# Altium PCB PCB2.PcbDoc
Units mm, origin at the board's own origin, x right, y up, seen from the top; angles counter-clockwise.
Board outline 152.4 x 101.6 mm, 2 copper layers (Top Layer, Bottom Layer); 14 components, 12 nets, 32 pads, 0 vias.
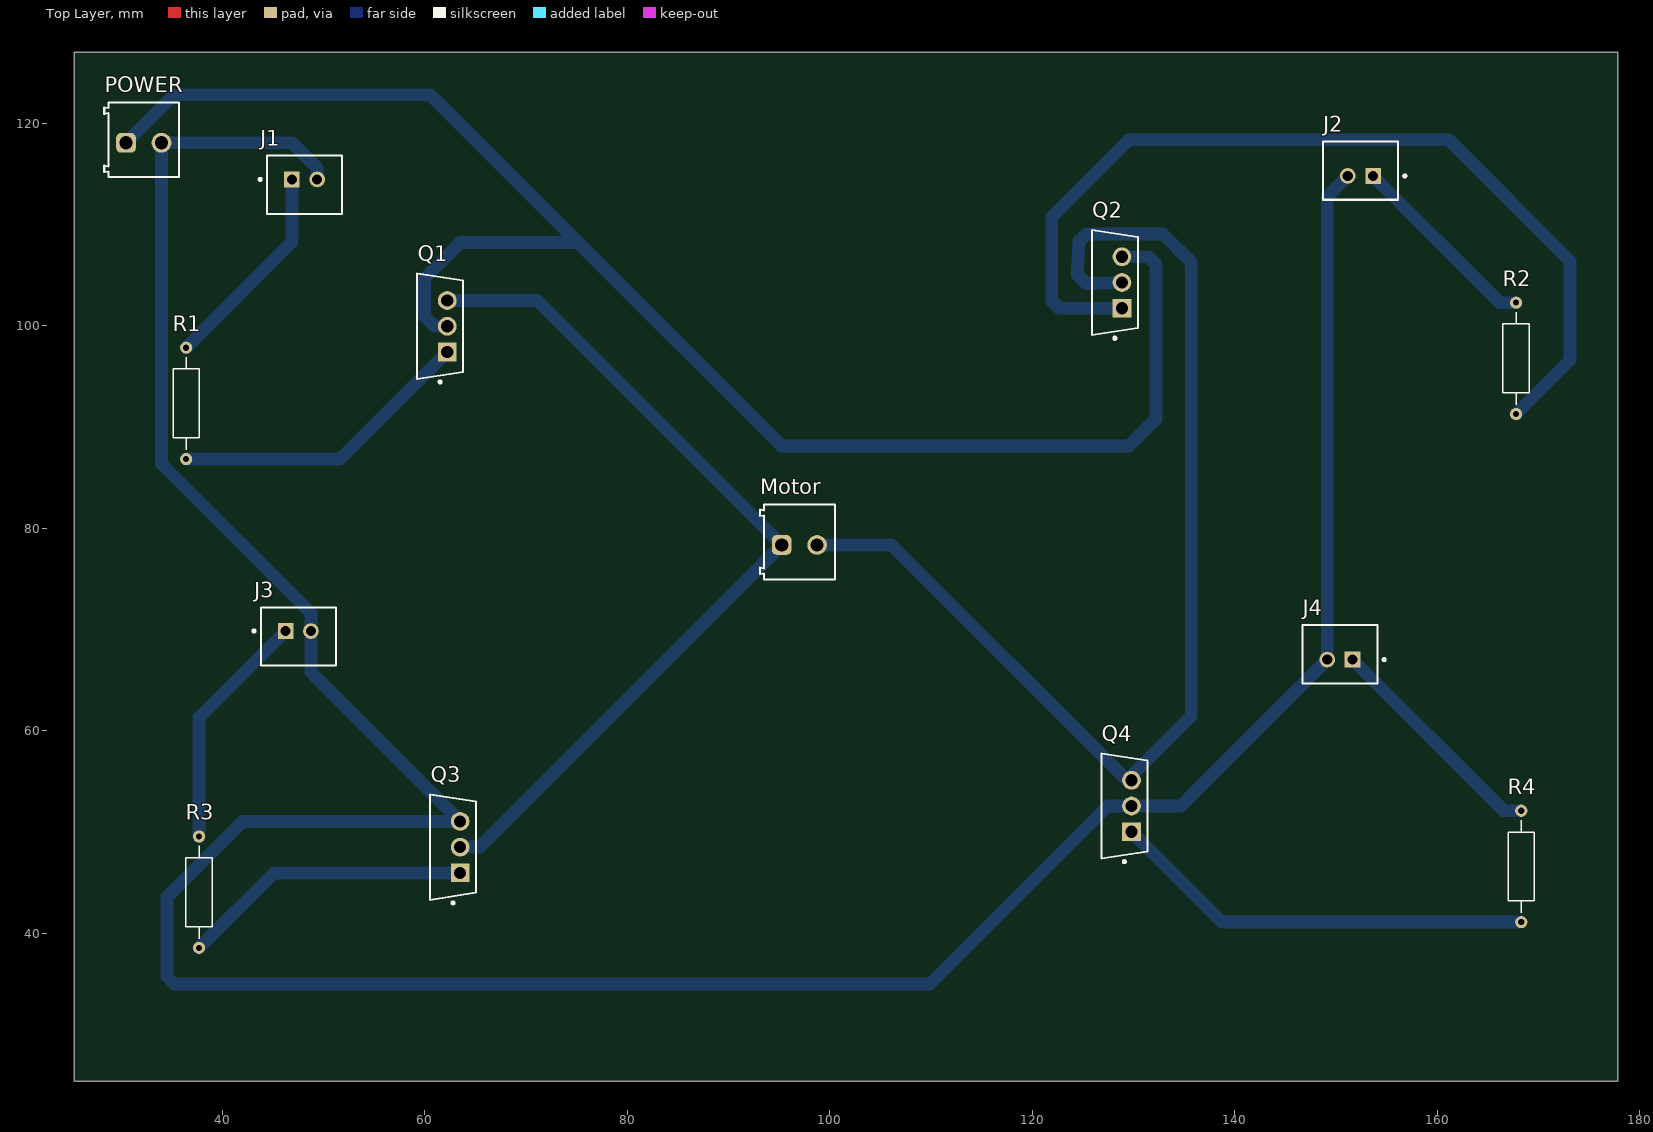
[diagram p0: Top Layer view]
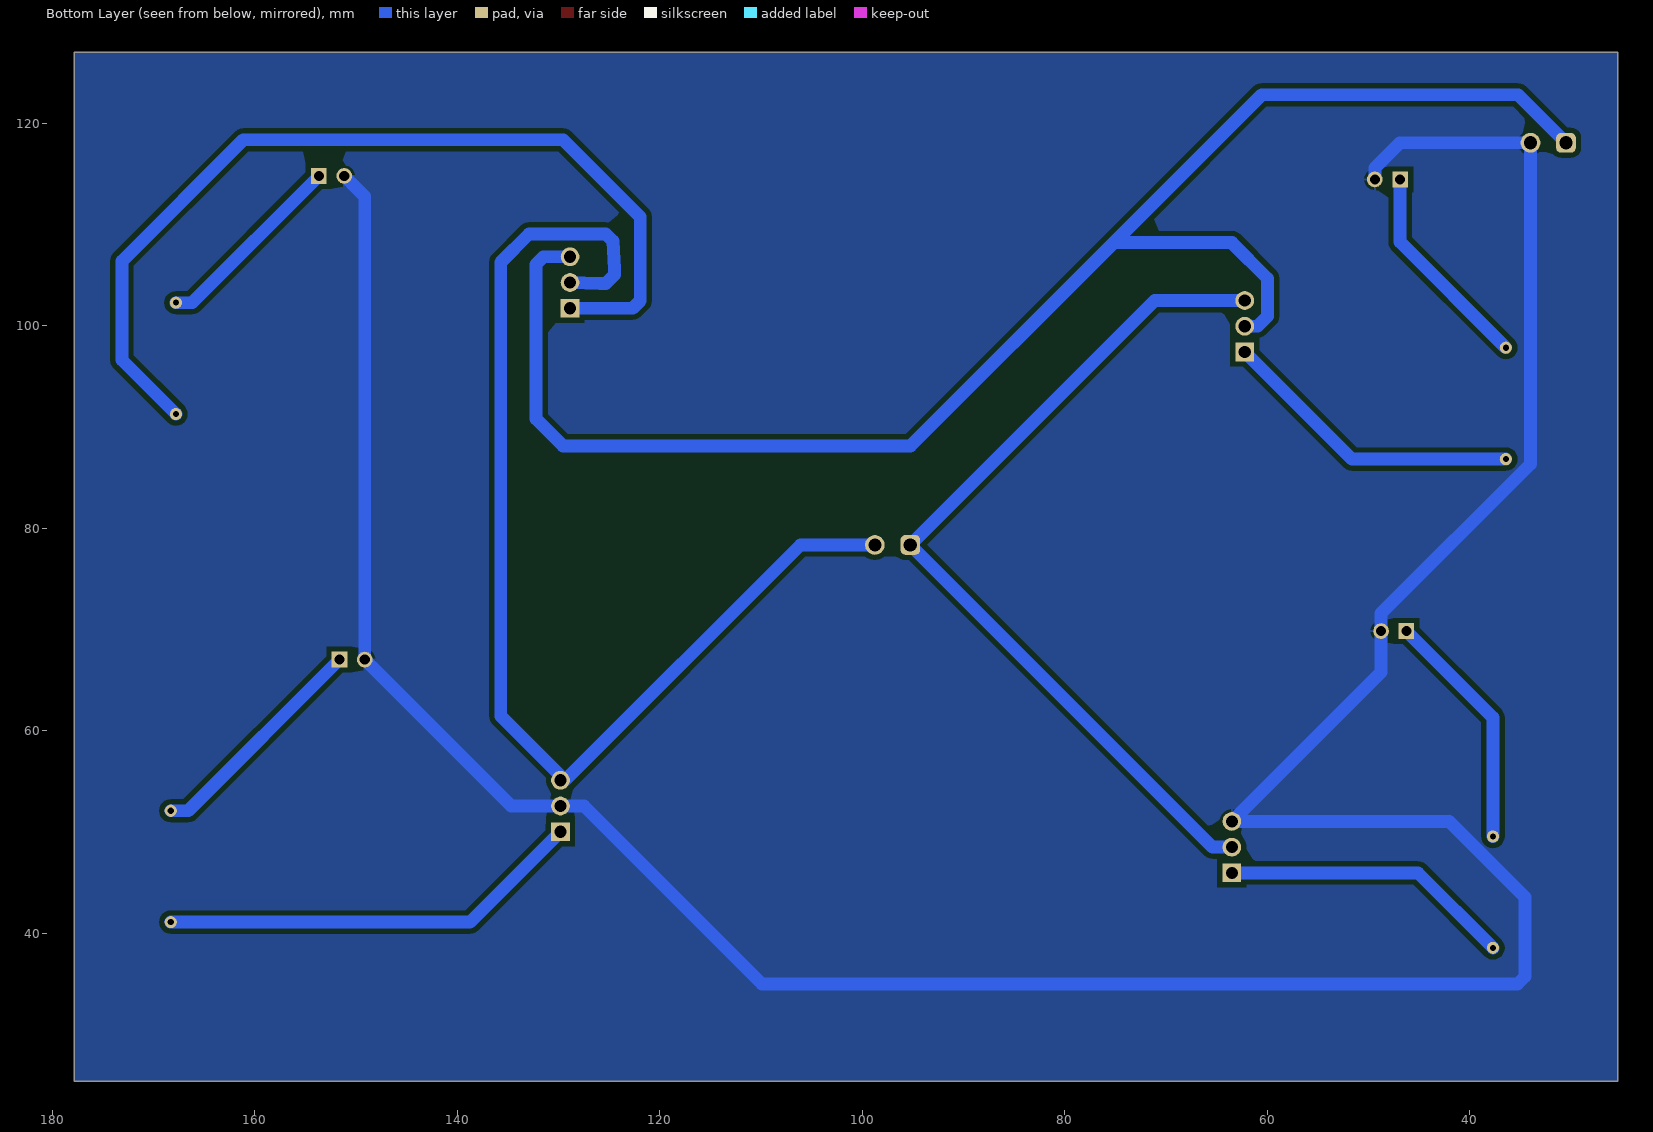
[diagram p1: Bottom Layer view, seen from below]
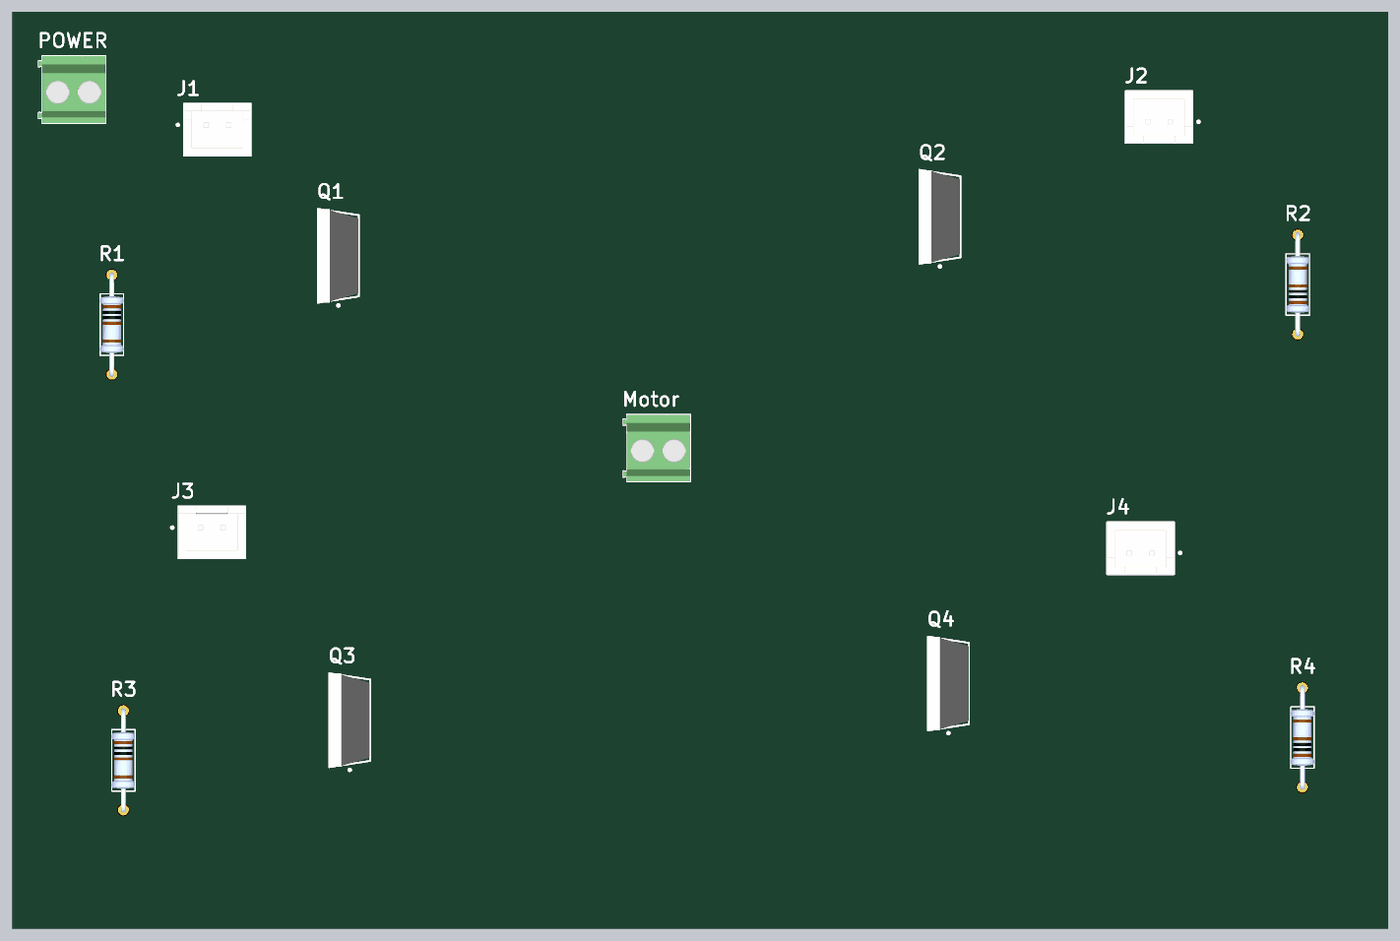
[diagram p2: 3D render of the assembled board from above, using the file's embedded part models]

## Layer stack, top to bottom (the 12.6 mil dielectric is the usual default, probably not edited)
Top Solder: solder mask 0.0102, Solder Resist, Dk 3.5
Top Layer: signal copper 0.0356
Dielectric 1: dielectric 0.32, FR-4, Dk 4.8
Bottom Layer: signal copper 0.0356
Bottom Solder: solder mask 0.0102, Solder Resist, Dk 3.5

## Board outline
25.4,25.4 177.8,25.4 177.8,127 25.4,127

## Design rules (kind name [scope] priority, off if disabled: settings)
Clearance [All] p1: gap=0.5 ignorepadtopadclearanceinfootprint=FALSE
PolygonConnect [All] p1: connectstyle=Relief reliefconductorwidth=0.254 reliefentries=4 polygonreliefangle="90 Angle" airgapwidth=0.254
RoutingVias [All] p1: holewidth=0.711 width=1.27 viastyle="Through Hole" minholewidth=0.711 minwidth=1.27 maxholewidth=0.711 maxwidth=1.27
SolderMaskExpansion [All] p1: expansion=0.102 istentingtop=FALSE
SupplyNets "Schematic Supply Nets_1" [InNet('VCC')] p1: voltage=0.000
SupplyNets "Schematic Supply Nets" [InNet('GND')] p2: voltage=0.000
Width [All] p1: maxlimit=2 minlimit=0.254 preferedwidth=1.27 toplayer_maxwidth=0.254 toplayer_prefwidth=0.254 bottomlayer_minwidth=1.27 minimp=50.000000 maximp=50.000000 favimp=50.000000
30 further rules are at their usual default settings.

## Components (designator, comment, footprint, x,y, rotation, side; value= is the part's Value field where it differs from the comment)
J1 "B2B-XH-A(LF)(SN)" "JST Connector" 48.133,113.919 r0 top
J2 "B2B-XH-A(LF)(SN)" "JST Connector" 152.4,115.316 r180 top
J3 "B2B-XH-A(LF)(SN)" "JST Connector" 47.518,69.325 r0 top
J4 "B2B-XH-A(LF)(SN)" "JST Connector" 150.368,67.564 r180 top
Motor "691214110002" "Terminal block" 97,78.659 r0 top
POWER "691214110002" "Terminal block" 32.258,118.364 r0 top
Q1 "IRF4905PBF" "Mosfet P-Ch" 61.525,99.949 r180 top
Q2 "IRF4905PBF" "Mosfet P-Ch" 128.143,104.267 r180 top
Q3 "IRLZ44NPbF" "MOSFET N-CH 55V 47A TO220AB" 62.795,48.514 r180 top
Q4 "IRLZ44NPbF" "MOSFET N-CH 55V 47A TO220AB" 129.089,52.578 r180 top
R1 "Resistor" Resistor 36.449,92.329 r270 top value=10K
R2 "Resistor" Resistor 167.767,96.774 r90 top value=10K
R3 "Resistor" Resistor 37.719,44.069 r270 top value=10K
R4 "Resistor" Resistor 168.275,46.609 r90 top value=10K

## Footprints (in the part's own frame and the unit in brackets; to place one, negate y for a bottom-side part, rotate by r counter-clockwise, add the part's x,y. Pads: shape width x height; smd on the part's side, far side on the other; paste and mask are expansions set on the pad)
"JST Connector" [mm] "FP-B2B-XH-A_LF_SN-MFG"
  rect 1.55x1.55 hole 1 paste-2539.97 mask+0: 1(-1.25,0.525)
  round 1.55 hole 1 paste-2539.97 mask+0: 2(1.25,0.525)
  silkscreen extent -4.5,-2.87 3.7,2.88, body extent -3.8,-2.98 3.8,2.98, height 0.25
"MOSFET N-CH 55V 47A TO220AB" [mm]
  rect 1.85x1.85 hole 1.2 paste-2539.97 mask+0: 1(-0.705,2.54)
  round 1.85 hole 1.2 paste-2539.97 mask+0: 2(-0.705,0) 3(-0.705,-2.54)
  silkscreen extent -2.28,-5.2 2.27,5.62, body extent -2.37,-5.55 2.37,5.55, height 0.25
"Mosfet P-Ch" [mm] "FP-PG-TO220-3-MFG"
  rect 1.85x1.85 hole 1.2 paste-2539.97 mask+0: 1(-0.705,2.54)
  round 1.85 hole 1.2 paste-2539.97 mask+0: 2(-0.705,0) 3(-0.705,-2.54)
  silkscreen extent -2.28,-5.2 2.27,5.62, body extent -2.37,-5.55 2.37,5.55, height 0.25
Resistor [mm]
  round 1.2 hole 0.6: 1(-5.5,0) 2(5.5,0)
  silkscreen extent -4.58,-1.3 4.58,1.3, body extent -5.77,-1.3 5.77,1.3, height 2.6
"Terminal block" [mm] "3.50 mm Horizontal Entry Modular, 2p"
  rrect50% 1.95x1.95 hole 1.3: 1(-1.75,-0.3)
  round 1.95 hole 1.3: 2(1.75,-0.3)
  silkscreen extent -3.9,-3.7 3.5,3.7, body extent -3.95,-3.7 3.5,3.7, height 8.55

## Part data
J1 J2 J3 J4: library part "jst connector", "CONN HEADER VERT 2POS 2.5MM", Color=Natural, Contact Resistance=20mR, Current Rating=3A, Housing Color=White, Insulation Resistance=1GR, Max Operating Temperature=85°C, Max Voltage Rating (AC)=250V, Min Operating Temperature=-25°C
Motor POWER: library part "Terminal block", Color="Blue, Green", Current=10A, Max Operating Temperature=105°C, Min Operating Temperature=-40°C, Voltage=300V
Q1 Q2: library part "Mosfet P-CH", "MOSFET P-CH 55V 74A TO-220AB", Case/Package=TO-220, Continuous Drain Current (ID)=74A, Drain to Source Breakdown Voltage=-55V, Drain to Source Resistance=20mR, Gate to Source Voltage (Vgs)=20V, Input Capacitance=3.4nF, Max Operating Temperature=175°C, Max Power Dissipation=200W, Min Operating Temperature=-55°C, Threshold Voltage=-4V
Q3 Q4: library part "MOSFET N-CH 55V 47A TO220AB", Case/Package=TO-220, Continuous Drain Current (ID)=47A, Drain to Source Breakdown Voltage=55V, Drain to Source Resistance=35mR, Gate to Source Voltage (Vgs)=16V, Input Capacitance=1.7nF, Max Operating Temperature=175°C, Max Power Dissipation=110W, Min Operating Temperature=-55°C, Threshold Voltage=2V
R1 R2 R3 R4: "10.2 kOhms Â±1% 0.25W, 1/4W Through Hole Resistor Axial - Metal Film", Package="Axial Yageo"

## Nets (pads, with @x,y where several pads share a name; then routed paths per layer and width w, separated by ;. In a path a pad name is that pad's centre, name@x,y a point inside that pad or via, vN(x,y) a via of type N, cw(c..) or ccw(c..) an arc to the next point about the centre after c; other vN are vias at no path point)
GND: J1.2 J2.2 J3.2 J4.2 POWER.2 Q3.3 Q4.2 | length 313.4
  Bottom Layer w1.27: J1.2 49.383,115.57 46.889,118.064 POWER.2 34.008,86.36 48.768,71.6 J3.2 48.768,65.786 Q3.3 42.037,51.054 34.544,43.561 34.544,35.745 35.288,35.001 109.906,35.001 127.483,52.578 Q4.2 134.657,52.578 J4.2 149.118,112.759 J2.2
MCU_1: J1.1 R1.1 | length 20.9
  Bottom Layer w1.27: R1.1 46.883,108.263 J1.1
MCU_2: J2.1 R2.2 | length 19.3
  Bottom Layer w1.27: J2.1 166.167,102.274 R2.2
MCU_3: J3.1 R3.1 | length 23.8
  Bottom Layer w1.27: R3.1 37.719,61.301 J3.1
MCU_4: J4.1 R4.2 | length 22.8
  Bottom Layer w1.27: J4.1 166.548,52.109 R4.2
NetMotor_1: Motor.1 Q1.3 Q3.2 | length 87.1
  Bottom Layer w1.27: Q1.3 71.12,102.489 Motor.1 65.405,48.514 Q3.2
NetMotor_2: Motor.2 Q2.2 Q4.3 | length 114.9
  Bottom Layer w1.27: Motor.2 106.105,78.359 129.346,55.118 Q4.3 129.794,55.566 135.696,61.468 135.696,106.274 132.902,109.068 125.329,109.068 124.615,108.353 124.458,105.593 124.458,105.031 125.329,104.16 125.882,104.16 Q2.2@128.828,104.285
NetQ1_1: Q1.1 R1.2 | length 30.2
  Bottom Layer w1.27: R1.2 51.65,86.829 Q1.1
NetQ2_1: Q2.1 R2.1 | length 92.1
  Bottom Layer w1.27: Q2.1 122.664,101.727 121.92,102.471 121.92,110.744 129.54,118.364 161.112,118.364 173.101,106.375 173.101,96.608 R2.1
NetQ3_1: Q3.1 R3.2 | length 28.8
  Bottom Layer w1.27: R3.2 45.124,45.974 Q3.1
NetQ4_1: Q4.1 R4.1 | length 42.2
  Bottom Layer w1.27: Q4.1 138.723,41.109 R4.1
VCC: POWER.1 Q1.2 Q2.3 | length 161.1
  Bottom Layer w1.27: POWER.1 35.253,122.809 60.554,122.809 75.159,108.204 ; Q1.2 60.96,99.949 59.969,100.94 59.969,104.673 63.5,108.204 75.159,108.204 ; Q2.3 131.463,106.807 132.207,106.063 132.207,90.805 129.54,88.138 95.225,88.138 75.159,108.204

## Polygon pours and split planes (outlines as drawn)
GND on Bottom Layer "GND_L02_P000" (solid, remove dead copper, pour order 0): 25.4,25.4 177.8,25.4 177.8,127 25.4,127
